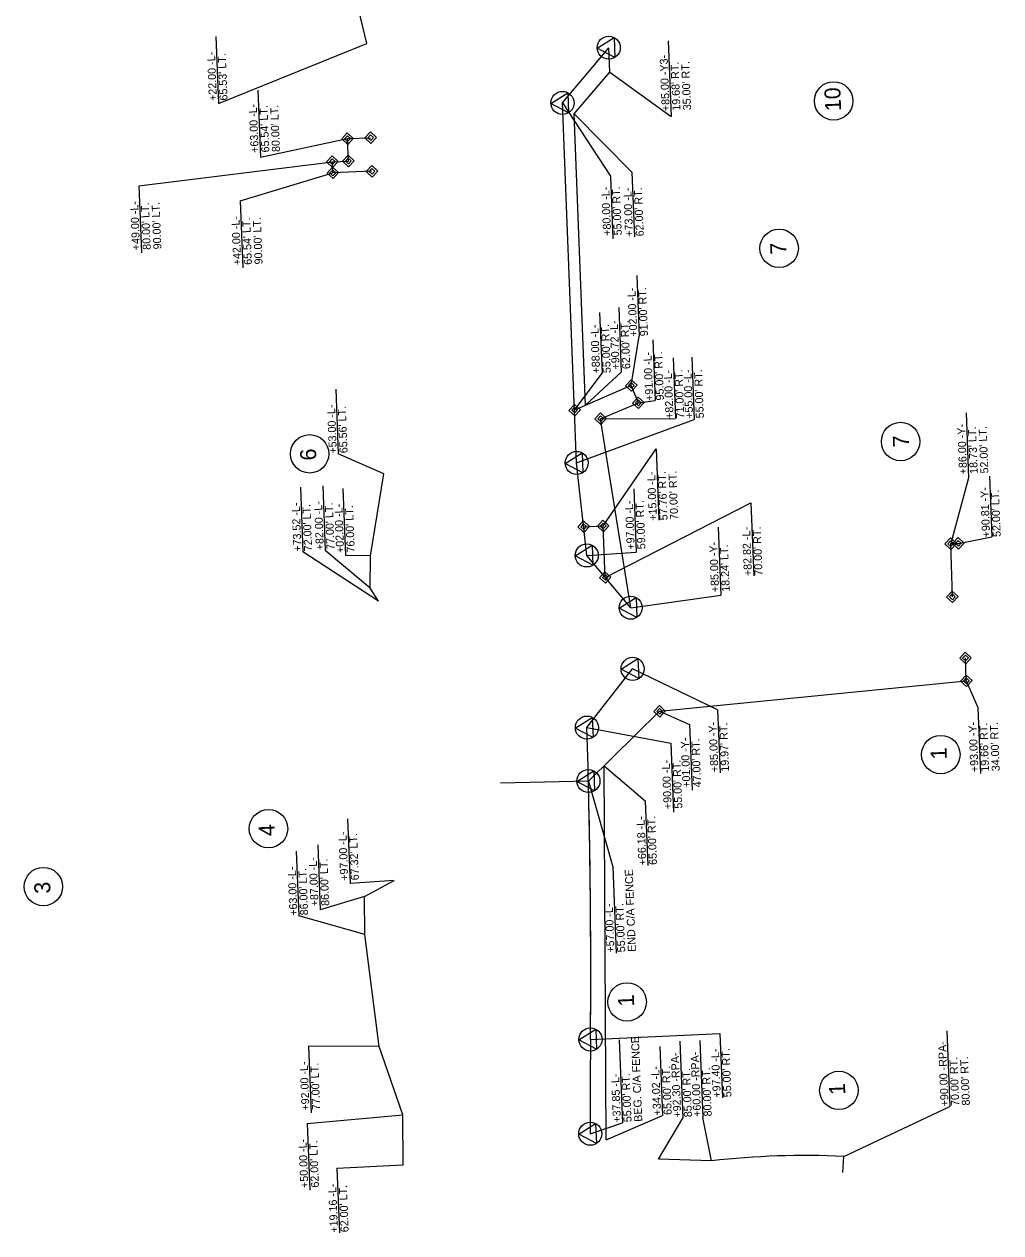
# Model space of a CAD drawing. Extents: x 1627970 to 1628801, y 761752 to 765698.
# Drawn here: x 1628191 to 1628801, y 761752 to 762507 of the extents above; entities that cross this region are included whole.
import ezdxf

# ---------------------------------------------------------------- set-up
doc = ezdxf.new("R2010")
doc.units = 0
for name, color, linetype in [('Exist Other Culture Gas Pump or Vent CELL', 7, 'Continuous'), ('Exist Other Culture Sign Post CELL', 7, 'Continuous'), ('Exist Property Line Leader', 7, 'Continuous'), ('Exist Property Line Text', 7, 'Continuous'), ('Exist Property Owner Number CELL', 7, 'Continuous'), ('Exist Right of Way Control of Access Line', 7, 'Continuous'), ('Exist Right of Way Monument Leader', 7, 'Continuous'), ('Exist Right of Way Monument Text', 7, 'Continuous'), ('Exist Roads Concrete Median Barrier', 7, 'Continuous'), ('Exist Roads EOT', 7, 'Continuous'), ('Exist Utilities Gas UG Line', 7, 'Continuous'), ('Exist Utilities Gas UG Line Text', 7, 'Continuous'), ('Exist Utilities Other Unknown UG SUE Text', 7, 'Continuous'), ('Scratch_Level_1', 7, 'Continuous')]:
    doc.layers.add(name, color=color, linetype=linetype)

msp = doc.modelspace()

# ---------------------------------------------------------------- linework, layer by layer
at = {"layer": 'Exist Other Culture Gas Pump or Vent CELL'}
for p, q in [((1628552.69, 762193.13), (1628585.67, 762241.28)), ((1628585.67, 762241.28), (1628587.43, 762196.66)), ((1628553.96, 762160.98), (1628644.95, 762207.56)), ((1628644.95, 762207.56), (1628646.75, 762162.09))]:
    msp.add_line(p, q, dxfattribs=at)
at = {"layer": 'Exist Other Culture Sign Post CELL'}
for centre, radius, start, end in [((1623719.93, 761914.16), 4825, 359.5044, 1.42141), ((1633259.57, 761831.64), 4715, 179.5044, 180.21971)]:
    msp.add_arc(centre, radius, start, end, dxfattribs=at)
at = {"layer": 'Exist Property Line Leader'}
for p, q in [((1628393.03, 762435.03), (1628407.48, 762435.6)), ((1628393.58, 762421.04), (1628393.03, 762435.03)), ((1628383.59, 762420.65), (1628393.58, 762421.04)), ((1628383.87, 762413.65), (1628383.59, 762420.65)), ((1628408.31, 762414.62), (1628383.87, 762413.65)), ((1628570.24, 762280.89), (1628534.82, 762265.48)), ((1628574.67, 762270.06), (1628570.24, 762280.89)), ((1628551.05, 762260.12), (1628574.67, 762270.06)), ((1628569.86, 762142.08), (1628551.05, 762260.12)), ((1628769.7, 762182.12), (1628774.51, 762182.27)), ((1628770.74, 762148.87), (1628769.7, 762182.12)), ((1628779.39, 762096.38), (1628778.94, 762110.71)), ((1628587.89, 762077.37), (1628779.39, 762096.38)), ((1628543.44, 762033.84), (1628587.89, 762077.37))]:
    msp.add_line(p, q, dxfattribs=at)
at = {"layer": 'Exist Property Line Text'}
for p, q in [((1628696.61, 762458.59), (1628696.61, 762458.59)), ((1628662.56, 762366.53), (1628662.56, 762366.53)), ((1628738.39, 762245.86), (1628738.39, 762245.86)), ((1628369.37, 762238.18), (1628369.37, 762238.18)), ((1628763.5, 762050.37), (1628763.5, 762050.37)), ((1628343.68, 762004.06), (1628343.68, 762004.06)), ((1628203.12, 761967.9), (1628203.12, 761967.9)), ((1628567.63, 761895.87), (1628567.63, 761895.87)), ((1628699.85, 761840.62), (1628699.85, 761840.62))]:
    msp.add_line(p, q, dxfattribs=at)
for centre in [(1628696.61, 762458.59), (1628662.56, 762366.53), (1628738.39, 762245.86), (1628369.37, 762238.18), (1628763.5, 762050.37), (1628343.68, 762004.06), (1628203.12, 761967.9), (1628567.63, 761895.87), (1628699.85, 761840.62)]:
    msp.add_circle(centre, 12, dxfattribs=at)
at = {"layer": 'Exist Property Owner Number CELL'}
for p in [(1628540.46, 762192.65), (1628553.96, 762160.98)]:
    msp.add_line(p, (1628552.69, 762193.13), dxfattribs=at)
at = {"layer": 'Exist Right of Way Control of Access Line'}
for p, q in [((1628527.26, 762457.34), (1628556.14, 762491.83)), ((1628536.12, 762232.51), (1628527.26, 762457.34)), ((1628542.41, 762174.71), (1628536.12, 762232.51)), ((1628569.86, 762142.08), (1628542.41, 762174.71)), ((1628542.5, 762067.21), (1628571.06, 762103.89))]:
    msp.add_line(p, q, dxfattribs=at)
msp.add_arc((1623719.93, 761914.16), 4825, 359.5044, 1.81779, dxfattribs=at)
at = {"layer": 'Exist Right of Way Monument Leader'}
for points in [[(1628389.44, 762434.89), (1628392.89, 762438.63), (1628396.63, 762435.17), (1628393.18, 762431.43)], [(1628391.23, 762434.96), (1628392.96, 762436.83), (1628394.83, 762435.1), (1628393.1, 762433.23)], [(1628403.89, 762435.46), (1628407.34, 762439.2), (1628411.08, 762435.74), (1628407.63, 762432)], [(1628405.69, 762435.53), (1628407.41, 762437.4), (1628409.28, 762435.67), (1628407.55, 762433.8)], [(1628380, 762420.5), (1628383.45, 762424.24), (1628387.19, 762420.79), (1628383.73, 762417.05)], [(1628381.79, 762420.58), (1628383.52, 762422.44), (1628385.39, 762420.72), (1628383.66, 762418.85)], [(1628389.99, 762420.9), (1628393.44, 762424.64), (1628397.18, 762421.18), (1628393.73, 762417.44)], [(1628391.79, 762420.97), (1628393.51, 762422.84), (1628395.38, 762421.11), (1628393.66, 762419.24)], [(1628380.27, 762413.51), (1628383.73, 762417.25), (1628387.46, 762413.79), (1628384.01, 762410.05)], [(1628382.07, 762413.58), (1628383.8, 762415.45), (1628385.67, 762413.72), (1628383.94, 762411.85)], [(1628404.71, 762414.47), (1628408.17, 762418.21), (1628411.91, 762414.76), (1628408.45, 762411.02)], [(1628406.51, 762414.54), (1628408.24, 762416.41), (1628410.11, 762414.69), (1628408.38, 762412.82)], [(1628566.65, 762280.75), (1628570.1, 762284.49), (1628573.84, 762281.03), (1628570.39, 762277.3)], [(1628568.45, 762280.82), (1628570.17, 762282.69), (1628572.04, 762280.96), (1628570.32, 762279.09)], [(1628571.08, 762269.92), (1628574.53, 762273.66), (1628578.27, 762270.2), (1628574.82, 762266.46)], [(1628572.88, 762269.99), (1628574.6, 762271.86), (1628576.47, 762270.13), (1628574.75, 762268.26)], [(1628531.23, 762265.34), (1628534.68, 762269.08), (1628538.42, 762265.63), (1628534.97, 762261.89)], [(1628533.03, 762265.41), (1628534.75, 762267.28), (1628536.62, 762265.56), (1628534.89, 762263.69)], [(1628547.45, 762259.98), (1628550.91, 762263.72), (1628554.64, 762260.26), (1628551.19, 762256.52)], [(1628549.25, 762260.05), (1628550.98, 762261.92), (1628552.85, 762260.19), (1628551.12, 762258.32)], [(1628536.86, 762192.51), (1628540.32, 762196.25), (1628544.06, 762192.79), (1628540.6, 762189.05)], [(1628549.09, 762192.99), (1628552.55, 762196.73), (1628556.28, 762193.27), (1628552.83, 762189.54)], [(1628538.66, 762192.58), (1628540.39, 762194.45), (1628542.26, 762192.72), (1628540.53, 762190.85)], [(1628550.89, 762193.06), (1628552.62, 762194.93), (1628554.49, 762193.2), (1628552.76, 762191.33)], [(1628766.1, 762181.98), (1628769.56, 762185.72), (1628773.3, 762182.26), (1628769.84, 762178.52)], [(1628767.9, 762182.05), (1628769.63, 762183.92), (1628771.5, 762182.19), (1628769.77, 762180.32)], [(1628770.91, 762182.13), (1628774.36, 762185.87), (1628778.1, 762182.41), (1628774.65, 762178.67)], [(1628772.71, 762182.2), (1628774.43, 762184.07), (1628776.3, 762182.34), (1628774.58, 762180.47)], [(1628550.36, 762160.84), (1628553.81, 762164.58), (1628557.55, 762161.12), (1628554.1, 762157.39)], [(1628552.16, 762160.91), (1628553.89, 762162.78), (1628555.75, 762161.05), (1628554.03, 762159.18)], [(1628767.15, 762148.72), (1628770.6, 762152.46), (1628774.34, 762149.01), (1628770.89, 762145.27)], [(1628768.95, 762148.79), (1628770.67, 762150.66), (1628772.54, 762148.94), (1628770.81, 762147.07)], [(1628775.35, 762110.57), (1628778.8, 762114.31), (1628782.54, 762110.85), (1628779.09, 762107.11)], [(1628777.15, 762110.64), (1628778.87, 762112.51), (1628780.74, 762110.78), (1628779.01, 762108.91)], [(1628775.8, 762096.24), (1628779.25, 762099.98), (1628782.99, 762096.52), (1628779.54, 762092.78)], [(1628777.59, 762096.31), (1628779.32, 762098.18), (1628781.19, 762096.45), (1628779.46, 762094.58)], [(1628584.3, 762077.23), (1628587.75, 762080.97), (1628591.49, 762077.51), (1628588.04, 762073.77)], [(1628586.1, 762077.3), (1628587.82, 762079.17), (1628589.69, 762077.44), (1628587.97, 762075.57)]]:
    msp.add_lwpolyline(points, close=True, dxfattribs=at)
at = {"layer": 'Exist Right of Way Monument Text'}
for p, q in [((1628405.16, 762494.55), (1628398.64, 762521.32)), ((1628556.92, 762476.53), (1628556.14, 762491.83)), ((1628534.53, 762450.62), (1628556.92, 762476.53)), ((1628541.71, 762268.48), (1628534.53, 762450.62)), ((1628407.31, 762174.39), (1628415.74, 762225.76)), ((1628407.1, 762154.37), (1628407.31, 762174.39)), ((1628412.43, 762146.09), (1628407.1, 762154.37)), ((1628554.62, 761809.82), (1628553.2, 762043.4)), ((1628403.69, 761961.62), (1628422.26, 761971.67)), ((1628403.87, 761938.05), (1628403.69, 761961.62)), ((1628412.71, 761868.07), (1628403.87, 761938.05)), ((1628427.57, 761825.41), (1628412.71, 761868.07)), ((1628427.72, 761794.17), (1628427.57, 761825.41)), ((1628620.38, 761796.64), (1628587.13, 761797.68)), ((1628702.41, 761789.43), (1628702.86, 761799.42))]:
    msp.add_line(p, q, dxfattribs=at)
msp.add_arc((1628679.23, 761275.95), 524, 87.4149, 96.44801, dxfattribs=at)
at = {"layer": 'Exist Roads Concrete Median Barrier'}
for centre, radius, start, end in [((1623719.93, 761914.16), 4825, 359.5044, 1.42141), ((1633259.57, 761831.64), 4715, 179.5044, 180.21971)]:
    msp.add_arc(centre, radius, start, end, dxfattribs=at)
at = {"layer": 'Exist Roads EOT'}
for p, q in [((1628337.03, 762465.4), (1628338.68, 762423.43)), ((1628338.68, 762423.43), (1628393.03, 762435.03)), ((1628262.76, 762405.57), (1628383.59, 762420.65)), ((1628325.95, 762396.28), (1628383.87, 762413.65)), ((1628262.76, 762405.57), (1628264.41, 762363.71)), ((1628325.95, 762396.28), (1628327.6, 762354.31)), ((1628573.69, 762349.52), (1628575.19, 762311.63)), ((1628550.48, 762326.49), (1628551.97, 762288.6)), ((1628570.24, 762280.89), (1628575.19, 762311.63)), ((1628583.68, 762309.39), (1628585.17, 762271.5)), ((1628596.36, 762298.17), (1628597.85, 762260.28)), ((1628534.82, 762265.48), (1628551.97, 762288.6)), ((1628574.67, 762270.06), (1628585.17, 762271.5)), ((1628779.28, 762263.89), (1628780.89, 762223.1)), ((1628551.05, 762260.12), (1628597.85, 762260.28)), ((1628780.89, 762223.1), (1628769.7, 762182.12)), ((1628793.98, 762224.17), (1628795.47, 762186.25)), ((1628774.51, 762182.27), (1628795.47, 762186.25)), ((1628779.39, 762096.38), (1628786.67, 762079.73)), ((1628587.89, 762077.37), (1628606.52, 762069.21)), ((1628786.67, 762079.73), (1628788.3, 762038.56)), ((1628606.52, 762069.21), (1628608.15, 762028.09))]:
    msp.add_line(p, q, dxfattribs=at)
at = {"layer": 'Exist Utilities Gas UG Line'}
for p, q in [((1628593.36, 762496.03), (1628595.22, 762448.93)), ((1628556.92, 762476.53), (1628595.22, 762448.93)), ((1628527.26, 762457.34), (1628557.21, 762411.65)), ((1628557.21, 762411.65), (1628558.76, 762372.37)), ((1628608.02, 762298.65), (1628609.56, 762259.67)), ((1628536.12, 762232.51), (1628609.56, 762259.67)), ((1628571.73, 762216.23), (1628573.28, 762176.83)), ((1628624.51, 762192.35), (1628626.19, 762149.81)), ((1628542.41, 762174.71), (1628573.28, 762176.83)), ((1628569.86, 762142.08), (1628626.19, 762149.81)), ((1628624.16, 762078.31), (1628571.06, 762103.89)), ((1628624.16, 762078.31), (1628625.71, 762039.03)), ((1628542.5, 762067.21), (1628594.89, 762057.55)), ((1628594.89, 762057.55), (1628596.59, 762014.4)), ((1628543.44, 762033.84), (1628558.74, 761980.27)), ((1628558.74, 761980.27), (1628560.87, 761926.28)), ((1628544.75, 761872.42), (1628625.55, 761876.09)), ((1628562.74, 761872.2), (1628564.79, 761820.41)), ((1628625.55, 761876.09), (1628627.13, 761835.97)), ((1628544.61, 761813.56), (1628564.79, 761820.41))]:
    msp.add_line(p, q, dxfattribs=at)
at = {"layer": 'Exist Utilities Gas UG Line Text'}
for p, q in [((1628310.72, 762498.88), (1628312.38, 762456.91)), ((1628312.38, 762456.91), (1628405.16, 762494.55)), ((1628534.53, 762450.62), (1628570.66, 762414.05)), ((1628570.66, 762414.05), (1628572.26, 762373.63)), ((1628562.4, 762329.56), (1628563.99, 762289.27)), ((1628541.71, 762268.48), (1628563.99, 762289.27)), ((1628385.66, 762278.6), (1628387.25, 762238.17)), ((1628415.74, 762225.76), (1628387.25, 762238.17)), ((1628377.56, 762218.25), (1628379.15, 762177.83)), ((1628363.57, 762217.39), (1628365.16, 762176.97)), ((1628390.19, 762216.57), (1628391.84, 762174.6)), ((1628412.43, 762146.09), (1628365.16, 762176.97)), ((1628407.1, 762154.37), (1628379.15, 762177.83)), ((1628407.31, 762174.39), (1628391.84, 762174.6)), ((1628553.2, 762043.4), (1628578.92, 762021.49)), ((1628578.92, 762021.49), (1628580.51, 761981.07)), ((1628393.02, 762010.31), (1628394.61, 761969.89)), ((1628374.41, 761993.91), (1628376.01, 761953.49)), ((1628361.05, 761990), (1628362.65, 761949.58)), ((1628422.26, 761971.67), (1628394.61, 761969.89)), ((1628403.69, 761961.62), (1628376.01, 761953.49)), ((1628403.87, 761938.05), (1628362.65, 761949.58)), ((1628600.59, 761871.33), (1628602.48, 761823.22)), ((1628612.96, 761871.81), (1628614.86, 761823.71)), ((1628767.36, 761877.82), (1628769.22, 761830.53)), ((1628412.71, 761868.07), (1628368.59, 761868.3)), ((1628368.59, 761868.3), (1628370.24, 761826.6)), ((1628588, 761868.05), (1628589.7, 761824.91)), ((1628367.83, 761819.97), (1628427.57, 761825.41)), ((1628702.86, 761799.42), (1628769.22, 761830.53)), ((1628367.83, 761819.97), (1628369.48, 761778.27)), ((1628554.62, 761809.82), (1628589.7, 761824.91)), ((1628587.13, 761797.68), (1628602.48, 761823.22)), ((1628620.38, 761796.64), (1628614.86, 761823.71)), ((1628386.36, 761792.09), (1628427.72, 761794.17)), ((1628386.36, 761792.09), (1628387.95, 761751.66))]:
    msp.add_line(p, q, dxfattribs=at)
at = {"layer": 'Exist Utilities Other Unknown UG SUE Text'}
for p, q in [((1628556.14, 762491.83), (1628556.14, 762491.83)), ((1628527.26, 762457.34), (1628527.26, 762457.34)), ((1628393.03, 762435.03), (1628393.03, 762435.03)), ((1628407.48, 762435.6), (1628407.48, 762435.6)), ((1628383.59, 762420.65), (1628383.59, 762420.65)), ((1628393.58, 762421.04), (1628393.58, 762421.04)), ((1628408.31, 762414.62), (1628408.31, 762414.62)), ((1628383.87, 762413.65), (1628383.87, 762413.65)), ((1628570.24, 762280.89), (1628570.24, 762280.89)), ((1628534.82, 762265.48), (1628534.82, 762265.48)), ((1628574.67, 762270.06), (1628574.67, 762270.06)), ((1628551.05, 762260.12), (1628551.05, 762260.12)), ((1628536.12, 762232.51), (1628536.12, 762232.51)), ((1628540.46, 762192.65), (1628540.46, 762192.65)), ((1628552.69, 762193.13), (1628552.69, 762193.13)), ((1628769.7, 762182.12), (1628769.7, 762182.12)), ((1628774.51, 762182.27), (1628774.51, 762182.27)), ((1628542.41, 762174.71), (1628542.41, 762174.71)), ((1628553.96, 762160.98), (1628553.96, 762160.98)), ((1628770.74, 762148.87), (1628770.74, 762148.87)), ((1628569.86, 762142.08), (1628569.86, 762142.08)), ((1628778.94, 762110.71), (1628778.94, 762110.71)), ((1628571.06, 762103.89), (1628571.06, 762103.89)), ((1628779.39, 762096.38), (1628779.39, 762096.38)), ((1628587.89, 762077.37), (1628587.89, 762077.37)), ((1628542.5, 762067.21), (1628542.5, 762067.21)), ((1628543.44, 762033.84), (1628543.44, 762033.84)), ((1628544.75, 761872.42), (1628544.75, 761872.42)), ((1628544.61, 761813.56), (1628544.61, 761813.56))]:
    msp.add_line(p, q, dxfattribs=at)
for points in [[(1628548.94, 762491.56), (1628559.5, 762498.2), (1628559.99, 762485.73)], [(1628520.05, 762457.07), (1628530.62, 762463.7), (1628531.11, 762451.24)], [(1628528.92, 762232.24), (1628539.48, 762238.88), (1628539.97, 762226.41)], [(1628535.2, 762174.44), (1628545.76, 762181.08), (1628546.26, 762168.61)], [(1628562.65, 762141.81), (1628573.22, 762148.45), (1628573.71, 762135.98)], [(1628563.85, 762103.62), (1628574.41, 762110.26), (1628574.91, 762097.79)], [(1628535.29, 762066.94), (1628545.86, 762073.58), (1628546.35, 762061.11)], [(1628536.24, 762033.57), (1628546.8, 762040.21), (1628547.29, 762027.74)], [(1628537.54, 761872.15), (1628548.11, 761878.79), (1628548.6, 761866.32)], [(1628537.4, 761813.29), (1628547.96, 761819.93), (1628548.46, 761807.46)]]:
    msp.add_lwpolyline(points, close=True, dxfattribs=at)
for centre in [(1628556.14, 762491.83), (1628527.26, 762457.34), (1628536.12, 762232.51), (1628542.41, 762174.71), (1628569.86, 762142.08), (1628571.06, 762103.89), (1628542.5, 762067.21), (1628543.44, 762033.84), (1628544.75, 761872.42), (1628544.61, 761813.56)]:
    msp.add_circle(centre, 7.2, dxfattribs=at)
at = {"layer": 'Scratch_Level_1'}
msp.add_line((1628543.44, 762033.84), (1628488.46, 762032.48), dxfattribs=at)

# ---------------------------------------------------------------- texts
at = {"layer": 'Exist Other Culture Gas Pump or Vent CELL'}
for s, p in [('+15.00 -L-', (1628586.26, 762196.5)), ("57.76' RT.", (1628592.92, 762196.76)), ("70.00' RT.", (1628599.58, 762197.02)), ('+82.82 -L-', (1628645.57, 762161.92)), ("70.00' RT.", (1628652.24, 762162.19))]:
    msp.add_text(s, height=5, rotation=92.25819, dxfattribs=at).set_placement(p)
at = {"layer": 'Exist Property Line Text'}
for s, p in [('10', (1628701.3, 762452.38)), ('7', (1628667.18, 762362.91)), ('7', (1628743.77, 762242.6)), ('6', (1628373.62, 762234.2)), ('1', (1628767.33, 762047.51)), ('4', (1628347.81, 761999.59)), ('3', (1628207.58, 761963.66)), ('1', (1628572.09, 761893.15)), ('1', (1628703.91, 761837.92))]:
    msp.add_text(s, height=10, rotation=92.25819, dxfattribs=at).set_placement(p)
at = {"layer": 'Exist Roads EOT'}
for s, p in [('+63.00 -L-', (1628337.56, 762426.25)), ("65.54' LT.", (1628344.22, 762426.51)), ("80.00' LT.", (1628350.89, 762426.78)), ('+49.00 -L-', (1628263.5, 762365.46)), ("80.00' LT.", (1628270.17, 762365.72)), ("90.00' LT.", (1628276.83, 762365.99)), ('+42.00 -L-', (1628326.69, 762356.06)), ("65.54' LT.", (1628333.36, 762356.33)), ("90.00' LT.", (1628340.02, 762356.59)), ('+02.00 -L-', (1628574.01, 762311.46)), ("91.00' RT.", (1628580.67, 762311.72)), ('+88.00 -L-', (1628550.8, 762288.43)), ("55.00' RT.", (1628557.46, 762288.69)), ('+91.00 -L-', (1628584, 762271.33)), ("95.00' RT.", (1628590.66, 762271.59)), ('+82.00 -L-', (1628596.68, 762260.11)), ("71.00' RT.", (1628603.34, 762260.37)), ('+86.00 -Y-', (1628779.94, 762225.5)), ("18.73' LT.", (1628786.6, 762225.76)), ("52.00' LT.", (1628793.26, 762226.02)), ('+90.81 -Y-', (1628794.3, 762186.11)), ("52.00' LT.", (1628800.96, 762186.37)), ('+93.00 -Y-', (1628787.03, 762039.5)), ("19.66' RT.", (1628793.69, 762039.76)), ("34.00' RT.", (1628800.35, 762040.02)), ('+01.00 -Y-', (1628607.25, 762029.7)), ("47.00' RT.", (1628613.91, 762029.96))]:
    msp.add_text(s, height=5, rotation=92.25819, dxfattribs=at).set_placement(p)
at = {"layer": 'Exist Utilities Gas UG Line'}
for s, p in [('+85.00 -Y3-', (1628594.26, 762452.31)), ("19.68' RT.", (1628600.93, 762452.58)), ("35.00' RT.", (1628607.59, 762452.84)), ('+80.00 -L-', (1628557.65, 762374.44)), ("55.00' RT.", (1628564.31, 762374.7)), ('+55.00 -L-', (1628608.93, 762260.18)), ("55.00' RT.", (1628615.59, 762260.44)), ('+97.00 -L-', (1628572.42, 762178.44)), ("59.00' RT.", (1628579.08, 762178.7)), ('+85.00 -Y-', (1628625.08, 762151.87)), ("18.24' LT.", (1628631.74, 762152.13)), ('+85.00 -Y-', (1628624.66, 762039.51)), ("19.97' RT.", (1628631.32, 762039.77)), ('+90.00 -L-', (1628595.49, 762016.39)), ("55.00' RT.", (1628602.15, 762016.65)), ('END C/A FENCE', (1628573.13, 761927.26)), ('+57.00 -L-', (1628559.81, 761926.73)), ("55.00' RT.", (1628566.47, 761926.99)), ('BEG. C/A FENCE', (1628577.11, 761821.12)), ('+97.40 -L-', (1628626.13, 761836.16)), ("55.00' RT.", (1628632.79, 761836.42)), ('+37.85 -L-', (1628563.78, 761820.59)), ("55.00' RT.", (1628570.44, 761820.86))]:
    msp.add_text(s, height=5, rotation=92.25819, dxfattribs=at).set_placement(p)
at = {"layer": 'Exist Utilities Gas UG Line Text'}
for s, p in [('+22.00 -L-', (1628311.47, 762458.67)), ("65.53' LT.", (1628318.13, 762458.93)), ('+73.00 -L-', (1628571.41, 762373.83)), ("62.00' RT.", (1628578.07, 762374.1)), ('+90.72 -L-', (1628562.99, 762290.96)), ("62.00' RT.", (1628569.65, 762291.22)), ('+53.00 -L-', (1628386.41, 762238.38)), ("65.56' LT.", (1628393.07, 762238.64)), ('+73.52 -L-', (1628364.31, 762177.17)), ("72.00' LT.", (1628370.97, 762177.44)), ('+82.00 -L-', (1628378.3, 762178.03)), ("77.00' LT.", (1628384.97, 762178.3)), ('+02.00 -L-', (1628390.94, 762176.35)), ("76.00' LT.", (1628397.6, 762176.62)), ('+66.18 -L-', (1628579.66, 761981.28)), ("65.00' RT.", (1628586.32, 761981.54)), ('+97.00 -L-', (1628393.51, 761971.66)), ("67.32' LT.", (1628400.17, 761971.92)), ('+87.00 -L-', (1628374.99, 761955.68)), ("86.00' LT.", (1628381.65, 761955.95)), ('+63.00 -L-', (1628361.8, 761949.79)), ("86.00' LT.", (1628368.46, 761950.05)), ('+90.00 -RPA-', (1628768.37, 761830.74)), ('+92.30 -RPA-', (1628601.47, 761823.7)), ('+60.00 -RPA-', (1628613.85, 761824.18)), ('+92.00 -L-', (1628369.34, 761828.09)), ("77.00' LT.", (1628376, 761828.35)), ("70.00' RT.", (1628775.04, 761831)), ("80.00' RT.", (1628781.7, 761831.27)), ('+34.02 -L-', (1628588.85, 761825.11)), ("65.00' RT.", (1628595.51, 761825.38)), ("85.00' RT.", (1628608.14, 761823.96)), ("80.00' RT.", (1628620.51, 761824.45)), ('+50.00 -L-', (1628368.58, 761779.76)), ("62.00' LT.", (1628375.24, 761780.02)), ('+19.16 -L-', (1628387.1, 761751.87)), ("62.00' LT.", (1628393.77, 761752.13))]:
    msp.add_text(s, height=5, rotation=92.25819, dxfattribs=at).set_placement(p)

doc.saveas('drawing.dxf')
